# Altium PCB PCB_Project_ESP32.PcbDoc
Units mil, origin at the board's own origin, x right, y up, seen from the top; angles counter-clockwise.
Board outline 3530 x 3380 mil, 2 copper layers (Top Layer, Bottom Layer); 23 components, 26 nets, 104 pads, 2 vias.
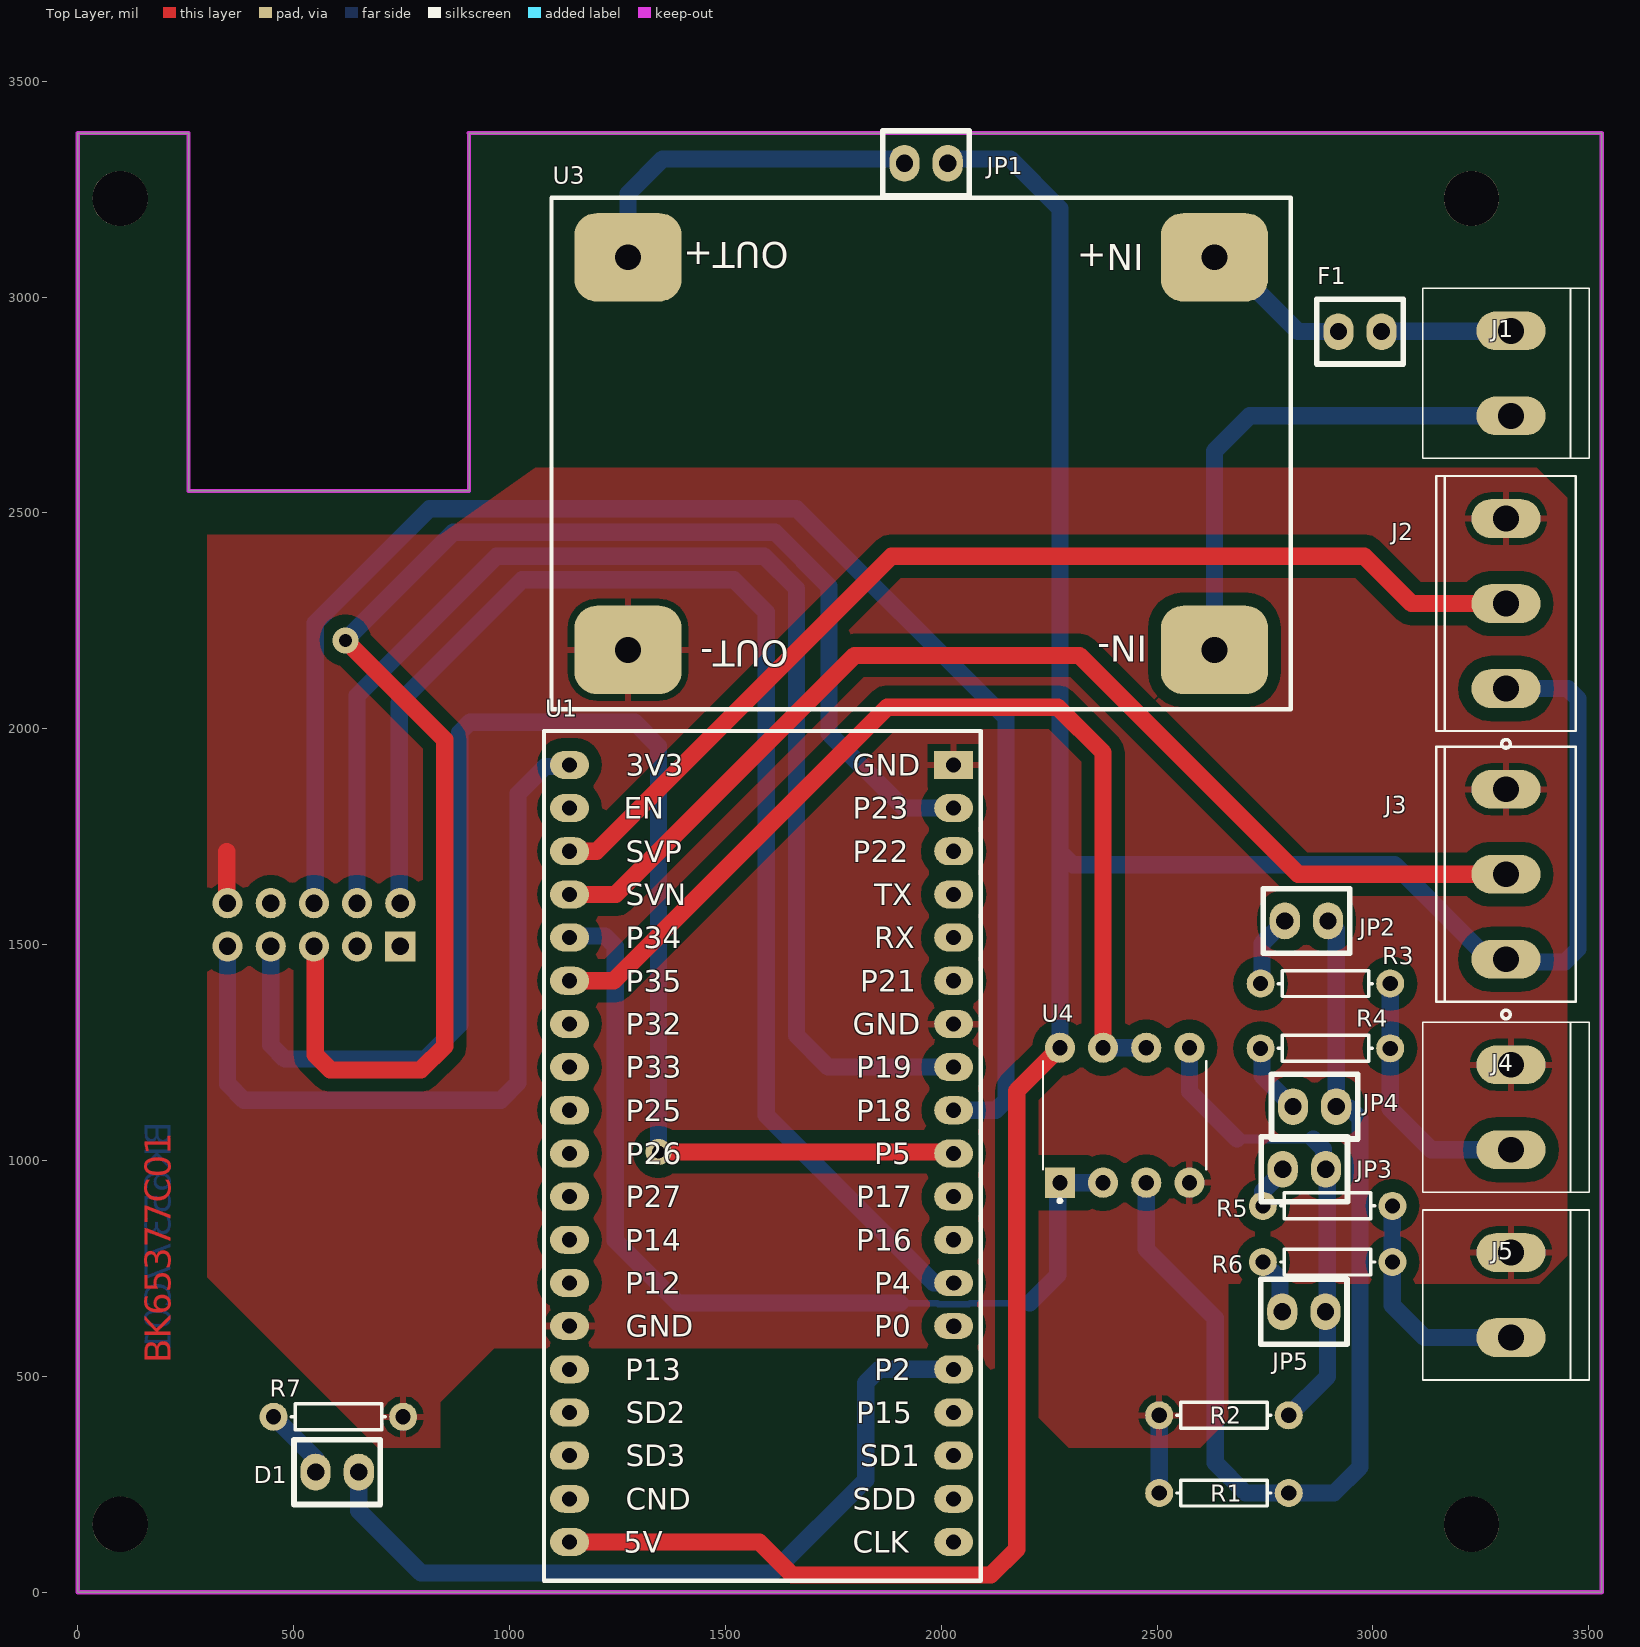
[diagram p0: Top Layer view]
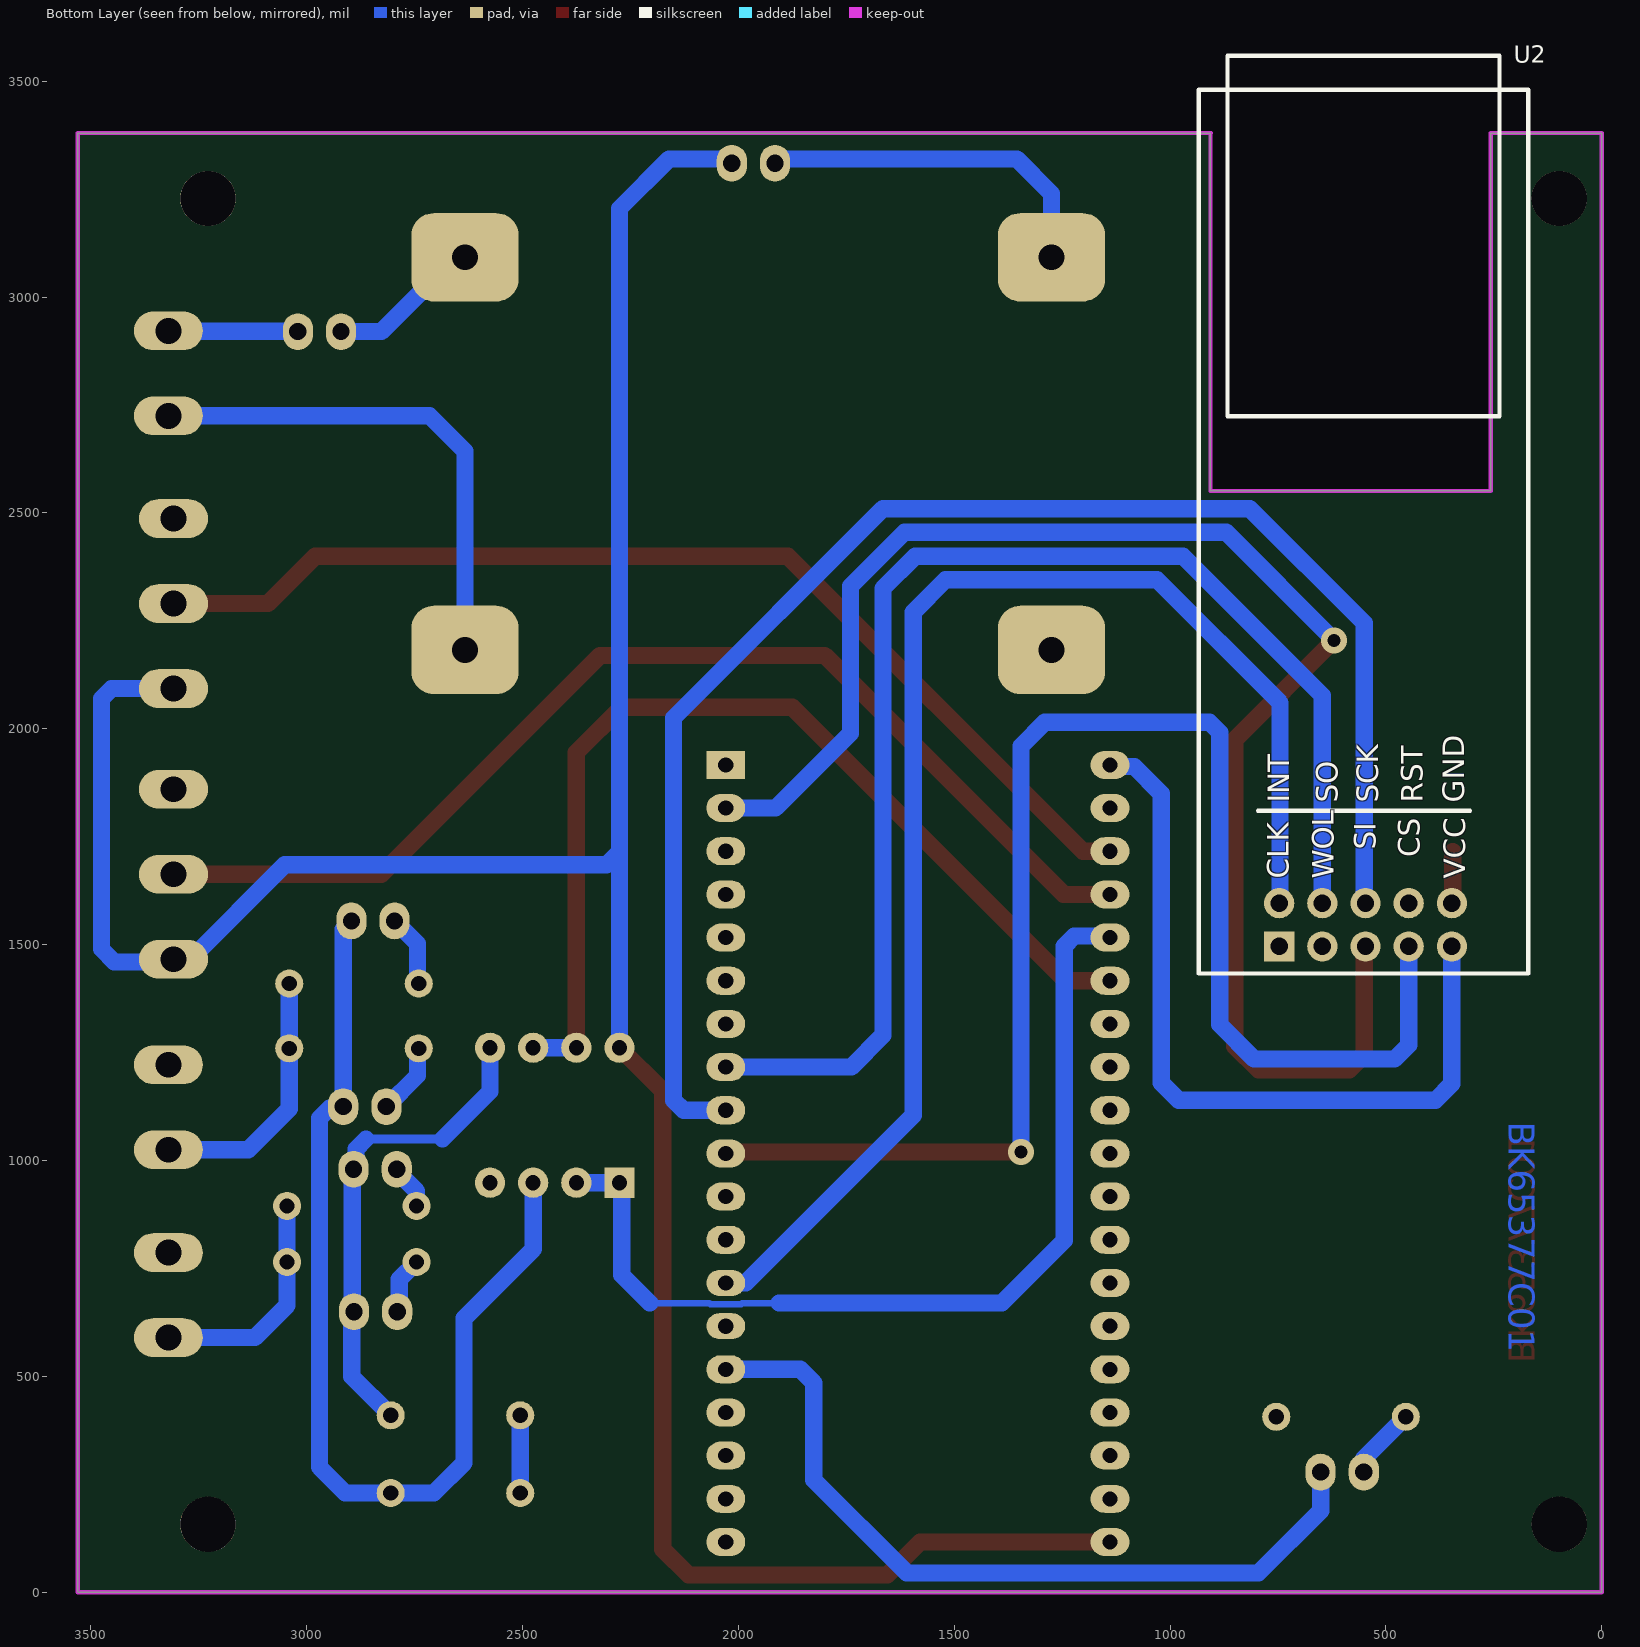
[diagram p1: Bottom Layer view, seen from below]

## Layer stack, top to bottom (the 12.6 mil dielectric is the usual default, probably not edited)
Top Solder: solder mask 0.4, Solder Resist, Dk 3.5
Top Layer: signal copper 1.4
Dielectric 1: dielectric 12.6, FR-4, Dk 4.8
Bottom Layer: signal copper 1.4
Bottom Solder: solder mask 0.4, Solder Resist, Dk 3.5

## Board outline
0,0 0,3380 256.81,3380 256.81,2550.91 906.42,2550.91 906.42,3380 3530,3380 3530,0

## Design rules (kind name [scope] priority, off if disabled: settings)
Clearance [All] p1: gap=10 ignorepadtopadclearanceinfootprint=FALSE
ComponentClearance [All] p1 off: gap=10 collisioncheckmode=3 verticalgap=10 showdistances=FALSE
HoleSize [All] p1: absolutevalues=TRUE maxlimit=200 minlimit=1 maxpercent=80.000 minpercent=20.000
MinimumAnnularRing [(ObjectKind = 'Pad') And (AsMils(HoleDiameter) = 128) And (AsMils(PadXSize_AllLayers) = 128) And (AsMils(PadYSize_AllLayers) = 128)] p1: minimumring=12
PolygonConnect [All] p1: connectstyle=Relief reliefconductorwidth=15 reliefentries=4 polygonreliefangle="90 Angle" airgapwidth=15
RoutingVias [All] p1: holewidth=28 width=50 viastyle="Through Hole" minholewidth=28 minwidth=50 maxholewidth=28 maxwidth=50
SolderMaskExpansion [All] p1: expansion=4 istentingtop=FALSE
Width [All] p1: maxlimit=80 minlimit=10 preferedwidth=40 minimp=50.000000 maximp=50.000000 favimp=50.000000
28 further rules are at their usual default settings.

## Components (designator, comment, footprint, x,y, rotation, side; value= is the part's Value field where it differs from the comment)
D1 "LED1" SIP2 651.13,278.48 r180 top
F1 "Fusible" sip2 2920,2920 r0 top
J1 "Alimentacion 48V" "BORNERA 2 (5MM)" 3320,2725 r90 top
J2 "Canal1" "BORNERA 3 (5MM)" 3308.2,2290 r90 top
J3 "Canal2" "BORNERA 3 (5MM)" 3308.2,1663.15 r90 top
J4 "Canal3" "BORNERA 2 (5MM)" 3320,1025 r90 top
J5 "Canal4" "BORNERA 2 (5MM)" 3320,590 r90 top
JP1 "Puente +5V" sip2 1915,3310 r0 top
JP2 "Puente CH3 +48V" sip2 2896,1555 r180 top
JP3 "Puente CH3 +24V" sip2 2815,1125 r0 top
JP4 "Puente CH4 +48V" sip2 2891,980 r180 top
JP5 "Puente CH4 +24V" SIP2 2790,650 r0 top
R1 "Res1" AXIAL-0.3 2655,230 r0 top
R2 "Res1" AXIAL-0.3 2655,410 r0 top
R3 "Res1" AXIAL-0.3 2890,1410 r0 top
R4 "Res1" AXIAL-0.3 2890,1260 r0 top
R5 "Res1" AXIAL-0.3 2895,895 r0 top
R6 "Res1" AXIAL-0.3 2895,765 r0 top
R7 "Res1" AXIAL-0.3 603.87,406.52 r0 top
U1 "ESP-32S V1.1" "ESP-32S V1.1" 1080,1995 r270 top
U2 "MODULO ETHERNET" "MODULO ETHERNET" 170,1433.11 r90 bottom
U3 "MODULO DC-DC" "MODULO DC-DC" 2810,3230 r180 top
U4 "TL082IP" DIP794W45P254L959H508Q8 2425,1105 r90 top

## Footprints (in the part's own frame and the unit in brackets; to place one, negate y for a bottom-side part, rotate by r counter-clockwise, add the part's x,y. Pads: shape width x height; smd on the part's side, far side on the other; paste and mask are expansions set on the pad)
AXIAL-0.3 [mil] "Axial Device, Thru-Hole; 2 Leads; 0.3 in Pin Spacing"
  round 65 hole 35 mask+6: 1(-150,0) 2(150,0)
  silkscreen extent -109,-30 109,30
"BORNERA 2 (5MM)" [mil] "BORNERA 2 (5MM)"
  oval 90x160 hole 60 mask+6: 1(0,0) 2(196.85,0)
  silkscreen extent -98,-181 295,205, body extent -122,-183 294,205, height 547
"BORNERA 3 (5MM)" [mil] "BORNERA 3 (5MM)"
  oval 90x160 hole 60 mask+6: 1(-196.85,0) 2(0,0) 3(196.85,0)
  silkscreen extent -335,-161 295,161, body extent -317,-164 297,159, height 397
DIP794W45P254L959H508Q8 [mil]
  rect 70x70 hole 35 mask+6: 1(-156.3,150)
  round 70 hole 35 mask+6: 2(-156.3,50) 3(-156.3,-50) 4(-156.3,-150) 5(156.3,-150) 6(156.3,-50) 7(156.3,50) 8(156.3,150)
  silkscreen extent -202,-189 125,189, body extent -164,-189 164,189, height 200
"ESP-32S V1.1" [mil]
  rect 65x90 hole 35 mask+6: 1(78.48,948.87)
  oval 65x90 hole 35 mask+6: 2(78.48,59.11) 3(178.48,948.87) 4(178.48,59.11) 5(278.48,948.87) 6(278.48,59.11) 7(378.48,948.87) 8(378.48,59.11) 9(478.48,948.87) 10(478.48,59.11) 11(578.48,948.87) 12(578.48,59.11) 13(678.48,948.87) 14(678.48,59.11) 15(778.48,948.87) 16(778.48,59.11) 17(878.48,948.87) 18(878.48,59.11) 19(978.48,948.87) 20(978.48,59.11) 21(1078.48,948.87) 22(1078.48,59.11) 23(1178.48,948.87) 24(1178.48,59.11) 26(1278.48,59.11) 28(1378.48,59.11) 29(1478.48,948.87) 30(1478.48,59.11) 31(1578.48,948.87) 32(1578.48,59.11) 33(1678.48,948.87) 34(1678.48,59.11) 35(1778.48,948.87) 36(1778.48,59.11) 37(1878.48,948.87) 38(1878.48,59.11)
  oval 60x90 hole 35.43 mask+6: 25(1278.48,948.87) 27(1378.48,948.87)
  silkscreen extent 0,0 1969,1012, body extent -2,-2 1964,1010, height 164
"MODULO DC-DC" [mm] "REG STEP DOWN LM2576HV DC-DC 5-60V"
  rrect50% 6.3x5.2 hole 1.524 mask+0.152: 1(4.5,26.6) 2(4.5,3.5) 3(39,3.5) 4(39,26.6)
  silkscreen extent 0,0 43.5,30.1, body extent -0.05,-0.13 43.54,30.2, height 13.2
"MODULO ETHERNET" [mil] "MOD ETHETNET ARDUINO HR911105A"
  rect 70x70 hole 40 paste+0 mask+6: 1(62.99,577.17)
  round 70 hole 40 paste+0 mask+6: 2(162.99,577.17) 3(62.99,477.17) 4(162.99,477.17) 5(62.99,377.17) 6(162.99,377.17) 7(62.99,277.17) 8(162.99,277.17) 9(62.99,177.17) 10(162.99,177.17)
  silkscreen extent 0,0 2126,764, body extent 1,-3 2126,766, height 535
SIP2 [mil]
  oval 70x85 hole 40 mask+6: 1(0,0) 2(100,0)
  silkscreen extent -50,-75 150,75
sip2 [mil]
  oval 70x85 hole 40 mask+6: 1(0,0) 2(100,0)
  silkscreen extent -50,-75 150,75

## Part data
D1: "Typical RED GaAs LED"
F1: library part "Fuse 1", "Fuse"
J1 J4 J5 JP1 JP2 JP3 JP4 JP5: library part "Header 2", "Header, 2-Pin"
J2 J3: library part "Header 3", "Header, 3-Pin"
R1 R2 R3 R4 R5 R6 R7: "Resistor"
U1: "ESP-32S V1.1 NODEMCU"
U2: "MOD ETHETNET ARDUINO HR911105A"
U3: "REG STEP DOWN LM2576HV DC-DC 5-60V"
U4: "Dual, 30-V, 3-MHz, 13-V/Âµs slew rate, In to V+, JFET-input op amp"

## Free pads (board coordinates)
  round 128 hole 128 mask+6: 2(98.43,157.48) 3(3228.35,157.48) 4(3228.35,3228.35) 5(98.43,3228.35)

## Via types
v1: diameter 60, hole 30, Top Layer to Bottom Layer, 2 vias

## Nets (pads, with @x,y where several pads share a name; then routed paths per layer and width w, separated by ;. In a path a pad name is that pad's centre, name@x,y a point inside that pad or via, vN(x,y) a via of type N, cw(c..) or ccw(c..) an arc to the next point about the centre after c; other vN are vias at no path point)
+3V3: U1.2 U2.9 | length 1840
  Bottom Layer w40: U2.9 347.17,1177.83 385,1140 980,1140 1020,1180 1020,1850 1082.87,1912.87 1135.46,1912.87 U1.2
+5: J2.1 J3.1 JP1.2 U1.38 U4.8 | length 6631.8
  Top Layer w40: U1.38 1578.48,116.52 1655,40 2115,40 2175,100 2175,1161.3 U4.8
  Bottom Layer w40: JP1.2@2004,3320 2160,3320 2275,3205 2275,1715 ; U4.8 2275,1715 ; J2.1 3451.57,2093.15 3475,2069.72 3475,1490 3445,1460 3314.5,1460 J3.1 3268.83,1466.3 3050.13,1685 2305,1685 2275,1715
GND: J2.3 J3.3 J4.2 J5.2 R1.1 R2.1 R7.2 U1.1 U1.13 U1.28 U2.10 U3.4 U4.4 | length 299.8
  Top Layer w40: 345,1715 345,1598.27 U2.10
  Bottom Layer w40: R1.1 R2.1
NetD1_1: D1.1 U1.29 | length 1854.1
  Bottom Layer w40: D1.1 651.13,188.87 795,45 1610,45 1825,260 1825,485 1856.52,516.52 U1.29
NetD1_2: D1.2 R7.1 | length 168.3
  Bottom Layer w40: R7.1 551.13,309.27 551.13,299.48 D1.2
NetF1_1: F1.1 U3.2 | length 368.5
  Bottom Layer w40: U3.2 2654.49,3092.2 2826.69,2920 F1.1@2930,2920
NetF1_2: F1.2 J1.2 | length 311.8
  Bottom Layer w40: F1.2@3009,2920 F1.2 3020.93,2920.93 3319.08,2920.93 J1.2
NetJ1_1: J1.1 U3.1 | length 1181.3
  Bottom Layer w40: U3.1 2632.84,2642.84 2715,2725 J1.1
NetJ2_2: J2.2 U1.6 | length 2497.8
  Top Layer w40: U1.6 1201.52,1716.52 1885,2400 2980,2400 3090,2290 J2.2
NetJ3_2: J3.2 U1.8 | length 2608.3
  Top Layer w40: U1.8 1246.52,1616.52 1800,2170 2320,2170 2826.85,1663.15 J3.2
NetJ4_1: J4.1 R3.2 R4.2 | length 609.4
  Bottom Layer w40: R3.2 R4.2 3040,1120 3135,1025 J4.1
NetJ5_1: J5.1 R5.2 R6.2 | length 536.1
  Bottom Layer w40: R5.2 R6.2 3045,665 3120,590 J5.1
NetJP1_1: JP1.1 U3.3 | length 831.1
  Bottom Layer w40: U3.3 1274.57,3239.57 1355,3320 JP1.1@1925,3320
NetJP2_1: JP2.1 JP3.2 R1.2 U4.3 | length 2414.7
  Bottom Layer w40: U4.3 2475,795 2635,635 2635,300 2705,230 2910,230 2970,290 2970,1098.32 2946.57,1121.75 JP3.2@2915,1121.75 ; JP2.1 2915,1536 JP3.2
NetJP2_2: JP2.2 R3.1 | length 168.2
  Bottom Layer w40: R3.1 2742.89,1412.89 2742.89,1501.89 JP2.2
NetJP3_1: JP3.1 R4.1 | length 166.1
  Bottom Layer w40: R4.1 2742.89,1257.11 2742.89,1197.11 JP3.1
NetJP4_1: JP4.1 JP5.2 R2.2 U4.5 | length 1124.9
  Bottom Layer w20: 2685,1050 2862.07,1050
  Bottom Layer w40: U4.5 2575,1160 2685,1050 ; R2.2 2895,500 2895,659 2894,660 2894,990 2885.5,998.5 2885.5,1026.57 2862.07,1050
NetJP4_2: JP4.2 R5.1 | length 106.6
  Bottom Layer w40: R5.1@2745.5,895 R5.1 2745,929 JP4.2@2796,980
NetJP5_1: JP5.1 R6.1 | length 131.6
  Bottom Layer w40: R6.1 2785,725 2785,690 JP5.1@2785,650
NetU1_3: U1.3 U2.5 | length 3602.1
  Top Layer w40: U2.5 550,1493.27 550,1245 585,1210 795,1210 850,1265 850,1975 v1(620,2205)
  Bottom Layer w40: v1(620,2205) 870,2455 1615,2455 1740,2330 1740,1990 1913.48,1816.52 2023.48,1816.52 2025,1815 2026.52,1816.52 U1.3
NetU1_10: U1.10 U4.1 U4.2 | length 2228.8
  Bottom Layer w15: 1905,670 1990.39,670 1993.37,667.02 2064.38,667.02 2067.36,670 2205,670
  Bottom Layer w40: U1.10 1142.59,1520 1221.57,1520 1245,1496.57 1245,815 1390,670 1905,670 ; 2205,670 2270,735 2270,943.7 U4.1 U4.2
NetU1_12: U1.12 U4.6 U4.7 | length 2325.5
  Top Layer w40: U1.12 1241.52,1416.52 1875,2050 2270,2050 2375,1945 U4.7
  Bottom Layer w40: U4.7 U4.6
NetU1_15: U1.15 U2.4 | length 3093
  Bottom Layer w40: U2.4 647.17,2077.17 970,2400 1590,2400 1665,2325 1665,1290 1738.48,1216.52 U1.15
NetU1_17: U1.17 U2.6 | length 3576.6
  Bottom Layer w40: U2.6 550,1598.94 550,2245 815,2510 1665,2510 2150,2025 2150,1140 2126.52,1116.52 U1.17
NetU1_19: U1.19 U2.7 | length 3507.2
  Top Layer w40: v1(1345,1020) 2025.39,1020 U1.19
  Bottom Layer w40: U2.7 447.17,1267.83 480,1235 805,1235 885,1315 885,1991.57 908.43,2015 1290,2015 1345,1960 v1(1345,1020)
NetU1_25: U1.25 U2.2 | length 3223.7
  Bottom Layer w40: U2.2 745,1598.27 745,2060 1030,2345 1520,2345 1595,2270 1595,1105 1982.87,717.13 2028.26,717.13 U1.25
pads on no net: U1.4 U1.5 U1.7 U1.9 U1.11 U1.14 U1.16 U1.18 U1.20 U1.21 U1.22 U1.23 U1.24 U1.26 U1.27 U1.30 U1.31 U1.32 U1.33 U1.34 U1.35 U1.36 U1.37 U2.1 U2.3 U2.8

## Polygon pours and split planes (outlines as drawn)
GND on Top Layer "Polygon1" (solid, remove dead copper, pour order 0): 300,2450 300,730 425,605 695,335 840,335 840,440 965,565 2065,565 2295,335 2600,335 2665,400 2665,715 3385,715 3450,780 3450,2535 3380,2605 1060,2605 840,2450 505,2450

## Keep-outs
Keep-Out Layer:
  lines w10: 255,3380 0,3380 0,0 3530,0 3530,3380 905,3380 ; 256.81,3380 256.81,2550.91 906.42,2550.91 906.42,3380

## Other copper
Top Layer:
  text "BK65377C01" at 215,530 h60 r90
Bottom Layer:
  text "BK65377C01" at 215,1090 h60 r90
